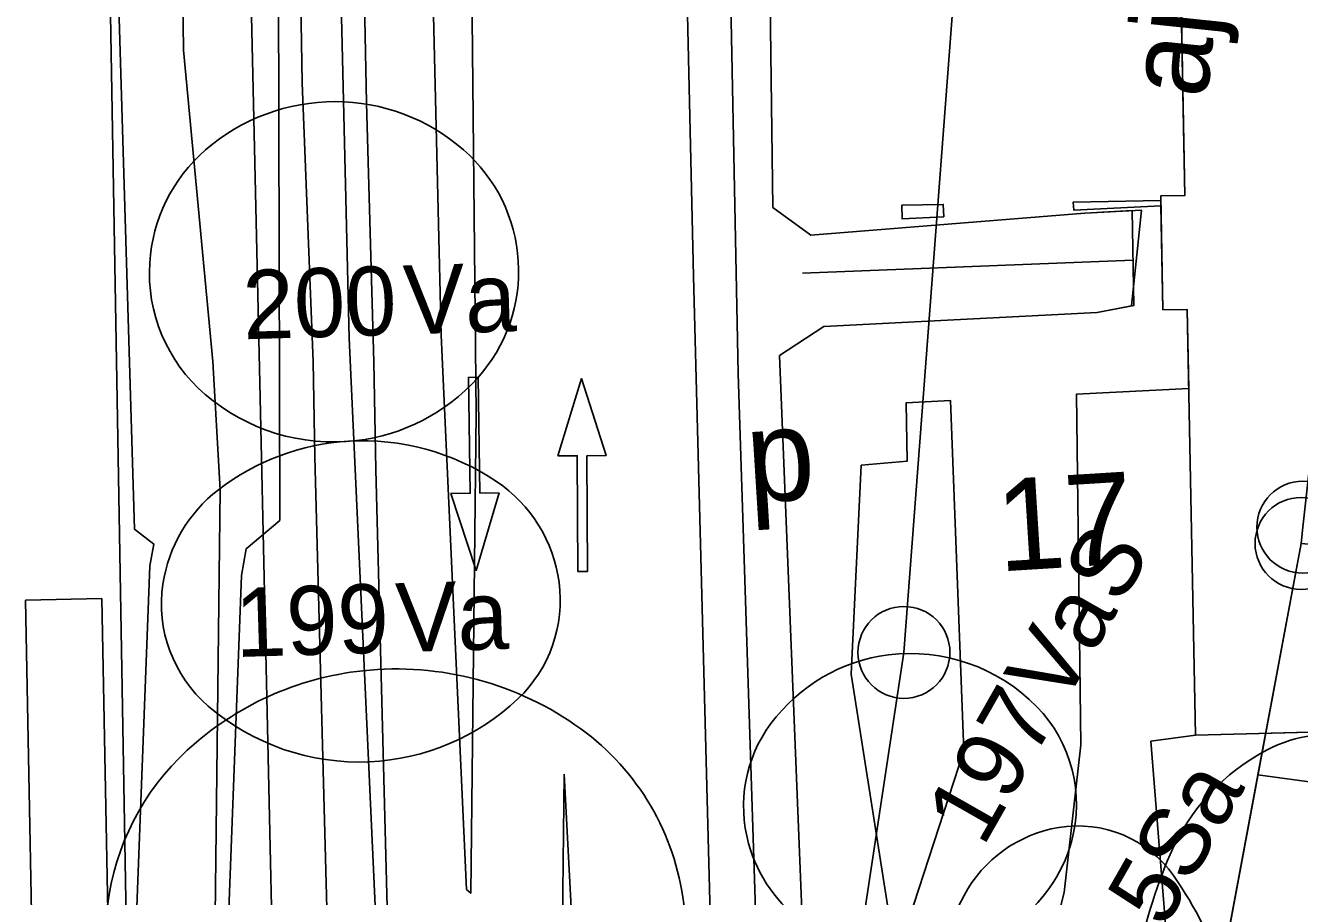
# Model space of a CAD drawing. Extents: x 738423 to 738903, y 6589762 to 6590172.
# Drawn here: x 738563.19 to 738590.9, y 6589890.45 to 6589909.4 of the extents above; entities that cross this region are included whole.
import ezdxf

# ---------------------------------------------------------------- set-up
doc = ezdxf.new("R2010")
doc.units = 0
for name, color, linetype in [('_1927_hoonestus', 7, 'Continuous'), ('_1927_katuse_kalded', 7, 'Continuous'), ('_1927_koordin_punktid_nr', 7, 'Continuous'), ('_1927_krundi_piir', 7, 'Continuous'), ('a_dendro_II_Vkl_puu', 7, 'Continuous'), ('a_dendro_III_vk_puu', 7, 'Continuous'), ('a_dendro_puu_nr', 7, 'Continuous'), ('Default', 7, 'Continuous'), ('plan_ala', 7, 'Continuous'), ('v_dp_jalak_liikumine', 7, 'Continuous'), ('v_olol_hoone', 7, 'Continuous'), ('v_olol_kitsendus_tehnov', 7, 'Continuous'), ('v_olol_sõidusuunad', 7, 'Continuous'), ('v_olol_transp_jjt_jalg', 7, 'Continuous'), ('v_olol_transp_tee', 7, 'Continuous'), ('v_vormistus_tekst', 7, 'Continuous')]:
    doc.layers.add(name, color=color, linetype=linetype)

# ---------------------------------------------------------------- blocks, each defined once
blk = doc.blocks.new('_U643')
at = {"layer": 'Default'}
for centre, radius, start, end in [((0.0018679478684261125, -0.01665713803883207), 0.02279509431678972, 71.14771462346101, 96.00680549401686), ((0.001839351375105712, -0.01638537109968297), 0.02252182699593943, 96.00680549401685, 121.28846409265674), ((0.0062500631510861, -0.0038231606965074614), 0.009233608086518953, 31.614909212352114, 71.14771462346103), ((-0.005254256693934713, -0.004713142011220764), 0.008863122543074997, 121.28846409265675, 162.12182872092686), ((0.009030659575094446, -0.0021115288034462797), 0.005968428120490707, 314.530794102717, 31.614909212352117), ((-0.008067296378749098, -0.00380573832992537), 0.00590735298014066, 162.12182872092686, 235.6485071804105), ((-0.000617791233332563, 0.007696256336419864), 0.019726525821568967, 274.44396782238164, 314.530794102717), ((-0.0005757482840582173, 0.0071552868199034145), 0.019183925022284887, 235.6485071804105, 274.44396782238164)]:
    blk.add_arc(centre, radius, start, end, dxfattribs=at)
blk = doc.blocks.new('_U644')
at = {"layer": 'Default'}
for centre, radius, start, end in [((0.00130196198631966, -0.010673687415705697), 0.016785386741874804, 66.2630147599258, 96.22277175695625), ((0.001280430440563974, -0.010476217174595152), 0.01658674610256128, 96.22277175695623, 126.90463232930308), ((0.005749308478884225, -0.0005600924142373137), 0.005737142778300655, 13.784006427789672, 66.26301475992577), ((-0.005344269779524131, -0.001654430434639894), 0.005554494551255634, 126.90463232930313, 181.31501957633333), ((0.006382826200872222, -0.0004046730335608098), 0.005084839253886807, 309.3713168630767, 13.784006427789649), ((-0.00581699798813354, -0.001665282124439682), 0.005081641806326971, 181.3150195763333, 241.68386791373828), ((-0.0007414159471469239, 0.008277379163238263), 0.01631572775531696, 274.75209171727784, 309.37131686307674), ((-0.000703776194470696, 0.007824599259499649), 0.015861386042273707, 241.68386791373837, 274.75209171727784)]:
    blk.add_arc(centre, radius, start, end, dxfattribs=at)
blk = doc.blocks.new('_U646')
at = {"layer": 'Default'}
for centre, radius, start, end in [((0.0015413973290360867, 0.0003312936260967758), 0.0060430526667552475, 57.797497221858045, 109.91963154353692), ((0.0016638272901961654, -6.553680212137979e-06), 0.006402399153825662, 109.91963154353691, 149.09162520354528), ((0.0007475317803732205, -0.000929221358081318), 0.007532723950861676, 11.452907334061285, 57.79749722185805), ((0.0028668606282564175, -0.000726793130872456), 0.007804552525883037, 149.09162520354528, 184.44182767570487), ((0.0005947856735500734, -0.0009601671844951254), 0.007688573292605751, 318.66315817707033, 11.452907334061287), ((0.0029452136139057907, -0.0007207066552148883), 0.00788314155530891, 184.44182767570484, 219.7138265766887), ((0.001892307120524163, -0.0015952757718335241), 0.006514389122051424, 219.71382657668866, 258.64991313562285), ((0.0018059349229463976, -0.002025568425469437), 0.006075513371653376, 258.64991313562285, 318.66315817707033)]:
    blk.add_arc(centre, radius, start, end, dxfattribs=at)
blk = doc.blocks.new('_U647')
at = {"layer": 'Default'}
for centre, radius, start, end in [((-0.001375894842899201, 0.00038972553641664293), 0.01064500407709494, 87.41040859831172, 137.64698014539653), ((-0.0013903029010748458, 7.115839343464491e-05), 0.01096389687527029, 46.91324083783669, 87.4104085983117), ((-0.003055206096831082, -0.0017088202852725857), 0.013401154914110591, 10.427707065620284, 46.91324083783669), ((0.0005566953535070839, -0.0013720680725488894), 0.013260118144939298, 137.64698014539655, 182.35571578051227), ((-0.0033161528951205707, -0.0017568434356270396), 0.013666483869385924, 328.31163123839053, 10.427707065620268), ((0.0007803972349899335, -0.0013628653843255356), 0.013484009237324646, 182.3557157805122, 228.78056258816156), ((-0.0010775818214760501, -0.003138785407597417), 0.011035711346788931, 281.1734997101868, 328.3116312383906), ((-0.0010219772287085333, -0.0034202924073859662), 0.010748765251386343, 228.7805625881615, 281.1734997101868)]:
    blk.add_arc(centre, radius, start, end, dxfattribs=at)
blk = doc.blocks.new('_U648')
at = {"layer": 'Default'}
for centre, radius, start, end in [((-0.0011014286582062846, 0.0021673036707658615), 0.005855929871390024, 85.75245550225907, 143.60493032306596), ((-0.0011389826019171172, 0.0016616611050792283), 0.0063629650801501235, 41.869521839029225, 85.75245550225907), ((0.002290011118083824, -0.000332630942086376), 0.010069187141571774, 143.60493032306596, 186.89560650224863), ((-0.0040701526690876, -0.0009655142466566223), 0.01029918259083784, 7.710312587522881, 41.86952183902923), ((-0.004202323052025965, -0.0009834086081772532), 0.010432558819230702, 330.4689955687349, 7.710312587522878), ((0.002267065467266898, -0.0003354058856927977), 0.010046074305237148, 186.89560650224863, 227.74554448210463), ((-0.0005955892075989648, -0.003026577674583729), 0.006287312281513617, 281.895410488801, 330.46899556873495), ((-0.0005169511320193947, -0.0033998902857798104), 0.005905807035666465, 227.74554448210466, 281.89541048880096)]:
    blk.add_arc(centre, radius, start, end, dxfattribs=at)
blk = doc.blocks.new('_U649')
at = {"layer": 'Default'}
for centre, radius, start, end in [((-0.0005806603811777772, 0.001035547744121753), 0.00697214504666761, 90.71533338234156, 143.60493033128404), ((-0.0005791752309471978, 0.0009165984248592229), 0.007091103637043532, 45.267207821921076, 90.71533338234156), ((-0.001635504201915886, -0.00014962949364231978), 0.00859199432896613, 4.178120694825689, 45.267207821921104), ((0.0007009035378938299, 9.086754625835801e-05), 0.008564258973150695, 143.60493033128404, 190.9882412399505), ((-0.001548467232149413, -0.00014327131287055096), 0.0085047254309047, 323.2193609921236, 4.178120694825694), ((0.0005592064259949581, 6.335459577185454e-05), 0.008419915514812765, 190.98824123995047, 232.2443045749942), ((-0.00035203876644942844, -0.0010376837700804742), 0.007010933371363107, 277.889093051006, 323.21936099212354), ((-0.00034315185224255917, -0.0011018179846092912), 0.006946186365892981, 232.24430457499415, 277.889093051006)]:
    blk.add_arc(centre, radius, start, end, dxfattribs=at)

msp = doc.modelspace()

# ---------------------------------------------------------------- linework, layer by layer
at = {"layer": '_1927_hoonestus'}
msp.add_lwpolyline([(738598.7561479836, 6589884.064893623), (738598.7561479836, 6589884.064893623), (738600.1654182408, 6589891.510843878), (738617.1576277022, 6589889.916511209), (738616.9587005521, 6589887.781161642), (738616.9587005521, 6589887.781161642), (738621.4793553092, 6589887.4869466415), (738621.2187353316, 6589884.178665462), (738631.1763472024, 6589883.225550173), (738634.3211426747, 6589909.080822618), (738624.2071897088, 6589909.313105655), (738622.5673353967, 6589895.324185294), (738590.9372064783, 6589898.13516685), (738590.9372064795, 6589898.13516685), (738586.1827055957, 6589872.62061175), (738613.3249623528, 6589869.722398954), (738613.2710881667, 6589869.728151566), (738614.3523733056, 6589877.812429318), (738614.3523733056, 6589877.812429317), (738614.3523733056, 6589877.812429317), (738615.0233334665, 6589882.235576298)], close=True, dxfattribs=at)
at = {"layer": '_1927_katuse_kalded'}
for points in [[(738589.9993202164, 6589893.102093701), (738590.9372064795, 6589898.13516685), (738597.9667878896, 6589897.510445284), (738597.1362287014, 6589892.057225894), (738595.5346271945, 6589892.346110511)], [(738586.1827055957, 6589872.62061175), (738591.5884234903, 6589872.043396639), (738595.5346271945, 6589892.346110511), (738589.9993202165, 6589893.102093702)]]:
    msp.add_lwpolyline(points, close=True, dxfattribs=at)
at = {"layer": '_1927_koordin_punktid_nr'}
for centre in [(738590.975352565, 6589898.488217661), (738590.9372064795, 6589898.13516685), (738582.2977970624, 6589895.764005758)]:
    msp.add_circle(centre, 0.9999999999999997, dxfattribs=at)
at = {"layer": '_1927_krundi_piir'}
for points in [[(738579.1301963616, 6589874.856906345), (738582.2977970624, 6589895.764005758), (738583.8997575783, 6589916.874257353), (738587.3009719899, 6589941.27260649), (738586.2348708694, 6589945.684910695), (738584.5188972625, 6589952.81209349)], [(738586.182705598, 6589872.620611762), (738590.9372064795, 6589898.13516685), (738590.975352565, 6589898.488217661), (738593.7110525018, 6589923.115674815), (738595.6482555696, 6589940.609766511), (738608.5799562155, 6589940.823351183), (738620.342268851, 6589941.795771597), (738638.2396178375, 6589940.94571321)]]:
    msp.add_lwpolyline(points, dxfattribs=at)
at = {"layer": 'Default'}
for points in [[(738581.2509999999, 6589869.558000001), (738581.073, 6589874.656), (738580.457, 6589879.119), (738580.1019999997, 6589889.433000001), (738579.5900000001, 6589902.219999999), (738580.555, 6589902.854999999), (738586.5010000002, 6589903.156999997), (738587.2448897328, 6589903.302988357), (738587.463427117, 6589905.386079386), (738586.2330000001, 6589905.318), (738580.2700000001, 6589904.839), (738579.4450000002, 6589905.446999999), (738579.2310000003, 6589922.173000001)], [(738577.3480000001, 6589920.061000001), (738577.716, 6589903.953000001), (738578.12, 6589888.683000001), (738578.3879999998, 6589878.424000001), (738579.014, 6589875.606999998), (738579.2310000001, 6589869.493000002)]]:
    msp.add_lwpolyline(points, dxfattribs=at)
at = {"layer": 'plan_ala'}
msp.add_lwpolyline([(738772.2221966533, 6589837.873120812), (738583.11, 6589865.669999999), (738583.11, 6589865.669999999), (738577.13, 6589865.85), (738565.7035831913, 6589866.139410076), (738565.4500000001, 6589885.77), (738564.4932191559, 6589941.052825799), (738581.9, 6589941.1499999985), (738615.11, 6589942.169999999), (738650.0499999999, 6589943.319999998), (738691.2690631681, 6589944.800325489), (738696.0901513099, 6589944.851371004), (738713.89, 6589945.129999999), (738703.51, 6589987.789999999), (738752.8799999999, 6590000.39), (738783.1408503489, 6590007.463828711), (738767.5688789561, 6589951.87996157)], close=True, dxfattribs=at)
at = {"layer": 'v_dp_jalak_liikumine'}
msp.add_line((738580.0898086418, 6589904.014712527), (738587.2818950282, 6589904.298363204), dxfattribs=at)
for points in [[(738580.8222069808, 6589853.375742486), (738579.8731274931, 6589862.502301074), (738579.7948247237, 6589868.094183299), (738580.455907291, 6589871.452329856), (738579.9085136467, 6589877.0110812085), (738579.325053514, 6589882.302804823), (738578.6922566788, 6589901.835364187), (738578.2534358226, 6589923.78491095), (738577.7643827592, 6589940.522382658), (738578.0100246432, 6589944.392285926), (738576.7151896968, 6589950.204053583)], [(738564.3587612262, 6589876.768792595), (738567.9129245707, 6589876.968967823), (738568.9682240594, 6589878.865942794), (738568.76067344, 6589880.123714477), (738568.2947477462, 6589901.299299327), (738567.7091425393, 6589926.873099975), (738566.992151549, 6589942.227474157), (738566.338151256, 6589947.998374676)]]:
    msp.add_lwpolyline(points, dxfattribs=at)
at = {"layer": 'v_olol_hoone'}
for points in [[(738588.6389999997, 6589893.962), (738599.4669999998, 6589894.244), (738599.3599151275, 6589899.873880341), (738600.996, 6589899.9049999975), (738601.01, 6589905.608999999), (738599.250746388, 6589905.613317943), (738598.9797844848, 6589919.858869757), (738600.6690000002, 6589919.891000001), (738600.5770000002, 6589925.68), (738598.8695780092, 6589925.652865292), (738598.69, 6589935.093999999), (738587.8449999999, 6589934.8719999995), (738588.023237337, 6589925.688511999), (738587.4179999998, 6589925.677), (738587.4650000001, 6589923.205999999), (738588.0711907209, 6589923.217765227), (738588.4110435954, 6589905.707209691), (738587.885, 6589905.696999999), (738587.9331245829, 6589903.217432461), (738588.4591681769, 6589903.227642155)], [(738563.1864886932, 6589896.902176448), (738564.8460000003, 6589896.936000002), (738565.0596708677, 6589885.967899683), (738563.3941039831, 6589885.935452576)]]:
    msp.add_lwpolyline(points, close=True, dxfattribs=at)
at = {"layer": 'v_olol_kitsendus_tehnov'}
for points in [[(738567.6884596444, 6589928.157698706), (738569.5640555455, 6589928.107424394), (738569.7442949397, 6589922.973568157), (738570.2308726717, 6589902.597054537), (738570.8235144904, 6589889.61800687), (738572.8972610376, 6589887.936315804), (738572.9818196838, 6589884.664234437), (738568.089969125, 6589886.902320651), (738567.5159941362, 6589887.676248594), (738567.8866814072, 6589897.433658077), (738567.9899137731, 6589898.018834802), (738568.721228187, 6589898.636862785), (738568.6597970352, 6589921.868076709)], [(738572.7804855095, 6589890.605993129), (738572.2297833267, 6589902.666549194), (738571.7671721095, 6589922.039412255), (738572.1701553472, 6589922.053990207), (738572.8992073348, 6589910.285745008), (738572.9891541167, 6589900.958059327), (738572.8764794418, 6589890.528147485)], [(738583.16354699, 6589905.239472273), (738582.2582836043, 6589905.193568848), (738582.2518938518, 6589905.49515928), (738583.1533325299, 6589905.510958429)], [(738582.0806785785, 6589888.9498845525), (738582.0888304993, 6589889.297274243), (738581.1487846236, 6589895.290815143), (738581.3691582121, 6589899.835374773), (738582.3698831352, 6589899.926173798), (738582.3430488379, 6589901.192727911), (738583.3139503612, 6589901.241959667), (738583.6007202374, 6589893.6200148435)], [(738574.904547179, 6589893.1154798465), (738575.1393173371, 6589888.692995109), (738575.0823527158, 6589888.739309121), (738574.8727855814, 6589888.909256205), (738574.8631395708, 6589889.282518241)]]:
    msp.add_lwpolyline(points, close=True, dxfattribs=at)
for points in [[(738564.7836066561, 6589924.311755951), (738565.5546792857, 6589898.442616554), (738565.977184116, 6589898.121736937), (738565.8933185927, 6589897.646341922), (738565.4958801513, 6589887.184775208), (738567.007573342, 6589884.061082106), (738566.9248224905, 6589883.548026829), (738566.9471825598, 6589883.201445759), (738566.5929069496, 6589879.151431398), (738565.5356253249, 6589879.141502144), (738565.5614588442, 6589877.14165656), (738568.4270930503, 6589877.168568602), (738568.4607498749, 6589877.553327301), (738568.8064016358, 6589873.915751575), (738567.5534011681, 6589873.878412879), (738565.6046055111, 6589873.801551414), (738565.6869613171, 6589867.426156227)], [(738591.66193984, 6589894.040728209), (738588.6389999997, 6589893.962), (738587.6660926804, 6589893.829031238), (738588.1662590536, 6589887.579376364), (738588.135796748, 6589886.714724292), (738584.7931808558, 6589886.641330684), (738585.7810944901, 6589890.54142003), (738586.1426695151, 6589893.750789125), (738586.0517247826, 6589901.380784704), (738588.4926106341, 6589901.504555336), (738588.4591681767, 6589903.227642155), (738587.933124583, 6589903.217432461), (738587.889229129, 6589905.479098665), (738585.9959303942, 6589905.383094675), (738585.9826741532, 6589905.560547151), (738587.8870005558, 6589905.593923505), (738587.8850000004, 6589905.697), (738588.4110435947, 6589905.707209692), (738588.3392058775, 6589909.602463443)]]:
    msp.add_lwpolyline(points, dxfattribs=at)
at = {"layer": 'v_olol_sõidusuunad'}
for points in [[(738573.491972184, 6589899.235273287), (738572.9921436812, 6589897.547613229), (738572.4420895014, 6589899.219577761), (738572.8620425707, 6589899.225855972), (738572.824373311, 6589901.745574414), (738573.0343498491, 6589901.748713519), (738573.0720191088, 6589899.228995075)], [(738574.7693176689, 6589900.03848548), (738575.285054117, 6589901.721352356), (738575.8193017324, 6589900.044270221), (738575.3993081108, 6589900.041956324), (738575.4131914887, 6589897.521994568), (738575.2031946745, 6589897.520837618), (738575.1893112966, 6589900.0407993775)]]:
    msp.add_lwpolyline(points, close=True, dxfattribs=at)
at = {"layer": 'v_olol_transp_jjt_jalg'}
for points in [[(738569.7619999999, 6589889.376999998), (738569.4820219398, 6589900.016635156), (738569.443999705, 6589902.0872306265), (738569.203, 6589908.154999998), (738568.9349999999, 6589924.352999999)], [(738581.2509999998, 6589869.558000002), (738581.073, 6589874.656), (738580.4569999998, 6589879.118999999), (738580.102, 6589889.433000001), (738579.5900000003, 6589902.219999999), (738580.555, 6589902.854999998), (738586.5010000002, 6589903.157000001), (738587.3010000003, 6589903.313999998), (738587.2610015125, 6589905.374879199), (738586.2329999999, 6589905.317999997), (738580.2699999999, 6589904.838999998), (738579.445, 6589905.446999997), (738579.2310000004, 6589922.1729999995)], [(738566.4630000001, 6589921.415), (738566.624, 6589908.864), (738567.2620837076, 6589902.095813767), (738567.4200000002, 6589899.302000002), (738567.308, 6589889.425)], [(738577.3479999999, 6589920.061), (738577.7159999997, 6589903.953), (738578.1199999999, 6589888.682999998), (738578.3879999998, 6589878.423999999), (738579.0140000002, 6589875.607), (738579.2310000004, 6589869.493000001)]]:
    msp.add_lwpolyline(points, dxfattribs=at)
at = {"layer": 'v_olol_transp_tee'}
for points in [[(738571.0769999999, 6589889.378), (738570.8110000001, 6589899.744), (738570.7640632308, 6589902.082037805), (738570.6019999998, 6589907.72), (738570.2520000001, 6589925.614999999)], [(738577.3479999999, 6589920.061), (738577.7159999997, 6589903.953), (738578.1199999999, 6589888.682999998), (738578.3879999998, 6589878.423999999), (738579.0140000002, 6589875.607), (738579.2310000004, 6589869.493000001)]]:
    msp.add_lwpolyline(points, dxfattribs=at)

# ---------------------------------------------------------------- block references
at = {"layer": 'a_dendro_II_Vkl_puu', "xscale": 500.0000000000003, "yscale": 500.0000000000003, "rotation": 85.69234851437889}
msp.add_blockref('_U643', (738590.191, 6589886.574999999), dxfattribs=at)
at = {"layer": 'a_dendro_III_vk_puu', "xscale": 500.0000000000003, "yscale": 500.0000000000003, "rotation": 85.69234851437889}
for name, p in [('_U649', (738569.9058187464, 6589904.271393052)), ('_U648', (738570.194, 6589897.284)), ('_U646', (738581.9369999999, 6589891.635)), ('_U647', (738570.5030000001, 6589890.29)), ('_U644', (738585.6409999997, 6589886.279))]:
    msp.add_blockref(name, p, dxfattribs=at)

# ---------------------------------------------------------------- texts
at = {"layer": '_1927_koordin_punktid_nr'}
for s, p in [('p', (738578.9203675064, 6589899.015664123)), ('17', (738584.3684448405, 6589897.522720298))]:
    msp.add_text(s, height=1.9999999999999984, rotation=3.560863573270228, dxfattribs=at).set_placement(p)
at = {"layer": 'a_dendro_puu_nr'}
for s, height, rotation, p in [('200', 1.5, 1.7381147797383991, (738567.933805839, 6589902.57482175)), ('Va', 1.5, 1.7381147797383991, (738571.4284455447, 6589902.680867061)), ('S', 1.4999999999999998, 60.34715687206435, (738587.015106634, 6589896.7715826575)), ('199', 1.5, 1.7381147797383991, (738567.7671022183, 6589895.662009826)), ('Va', 1.5, 1.7381147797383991, (738571.2617419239, 6589895.768055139)), ('Va', 1.4999999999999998, 60.34715687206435, (738585.7470309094, 6589894.544151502)), ('197', 1.4999999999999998, 60.34715687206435, (738584.0172845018, 6589891.505775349)), ('5Sa', 1.4999999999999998, 60.34715687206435, (738587.9634097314, 6589889.728261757))]:
    msp.add_text(s, height=height, rotation=rotation, dxfattribs=at).set_placement(p)
at = {"layer": 'v_vormistus_tekst'}
msp.add_text('ajalooline Suur tänav', height=1.7999999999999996, rotation=84.01099920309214, dxfattribs=at).set_placement((738588.8891757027, 6589907.796530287))

doc.saveas('drawing.dxf')
